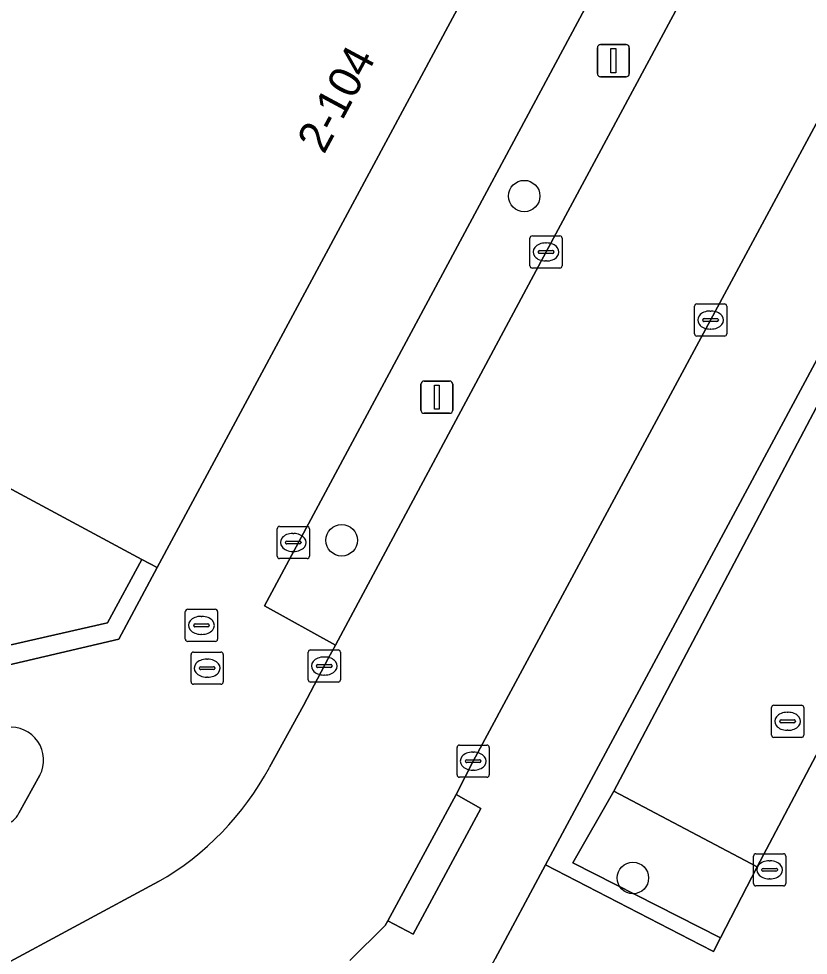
# Model space of a CAD drawing. Extents: x 159489 to 160304, y 383825 to 384531.
# Drawn here: x 159607.69 to 159632.19, y 384161.19 to 384190.24 of the extents above; entities that cross this region are included whole.
import ezdxf

# ---------------------------------------------------------------- set-up
doc = ezdxf.new("R2010")
doc.units = 0
for name, color, linetype in [('IMGEO_Boom', 7, 'Continuous'), ('IMGEO_Erf', 7, 'Continuous'), ('IMGEO_Groenvoorziening', 7, 'Continuous'), ('IMGEO_Haag', 7, 'Continuous'), ('IMGEO_Kolk', 7, 'Continuous'), ('IMGEO_Lichtmast', 7, 'Continuous'), ('IMGEO_Pand', 7, 'Continuous'), ('IMGEO_Pand_nummerreeks', 7, 'Continuous'), ('IMGEO_Parkeervlak_open', 7, 'Continuous'), ('IMGEO_Rijbaan_lokaal_gesloten', 7, 'Continuous'), ('IMGEO_Rijbaan_lokaal_open', 7, 'Continuous'), ('IMGEO_Rioolput', 7, 'Continuous'), ('IMGEO_Voetpad_open', 7, 'Continuous')]:
    doc.layers.add(name, color=color, linetype=linetype)

msp = doc.modelspace()

# ---------------------------------------------------------------- linework, layer by layer
at = {"layer": 'IMGEO_Boom'}
for centre in [(159623.374, 384184.738), (159617.709, 384174.062), (159626.747, 384163.584)]:
    msp.add_circle(centre, 0.489, dxfattribs=at)
at = {"layer": 'IMGEO_Erf'}
msp.add_lwpolyline([(159585.772, 384220.436), (159598.102, 384213.824), (159584.34, 384188.267), (159591.297, 384176.816), (159590.869, 384176.557), (159592.722, 384173.505), (159593.148, 384173.767), (159596.495, 384168.323), (159610.44, 384171.495), (159611.51, 384173.469), (159596.947, 384181.297), (159609.875, 384205.335), (159601.626, 384209.778), (159602.531, 384211.447), (159614.722, 384234.18)], dxfattribs=at)
at = {"layer": 'IMGEO_Groenvoorziening'}
for points in [[(159637.45, 384187.678), (159638.592, 384189.885), (159647.537, 384206.76), (159652.006, 384204.401), (159652.186, 384204.749), (159647.326, 384207.335), (159624.039, 384163.992), (159628.847, 384161.508), (159629.249, 384161.301), (159629.469, 384161.725), (159624.879, 384164.058), (159626.156, 384166.276)], [(159631.422, 384196.726), (159631.805, 384197.437), (159629.581, 384198.613), (159615.312, 384172.029), (159617.514, 384170.805), (159624.053, 384183.005)], [(159611.986, 384173.213), (159611.51, 384173.469), (159610.44, 384171.495), (159596.495, 384168.323), (159593.148, 384173.767), (159592.722, 384173.505), (159596.345, 384167.614), (159610.792, 384170.994)], [(159626.156, 384166.276), (159624.879, 384164.058), (159629.469, 384161.725), (159630.608, 384163.927)]]:
    msp.add_lwpolyline(points, close=True, dxfattribs=at)
msp.add_lwpolyline([(159607.686, 384165.591), (159608.344, 384166.77)], dxfattribs=at)
for centre, radius, start, end in [((159607.432, 384167.239), 1.025, 332.7949, 96.4671), ((159607.102, 384165.875), 0.65, 286.2159, 334.0909)]:
    msp.add_arc(centre, radius, start, end, dxfattribs=at)
at = {"layer": 'IMGEO_Haag'}
msp.add_lwpolyline([(159637.45, 384187.678), (159638.592, 384189.885), (159647.537, 384206.76), (159652.006, 384204.401), (159652.186, 384204.749), (159647.326, 384207.335), (159624.039, 384163.992), (159628.847, 384161.508), (159629.249, 384161.301), (159629.469, 384161.725), (159624.879, 384164.058), (159626.156, 384166.276)], close=True, dxfattribs=at)
at = {"layer": 'IMGEO_Kolk'}
for p, q in [((159623.552, 384182.579), (159623.552, 384183.431)), ((159623.627, 384183.505), (159624.479, 384183.505)), ((159624.04, 384183.285), (159624.065, 384183.285)), ((159624.553, 384183.431), (159624.553, 384182.579)), ((159623.811, 384182.999), (159623.811, 384183.011)), ((159624.249, 384182.962), (159623.851, 384182.962)), ((159623.854, 384183.048), (159624.252, 384183.048)), ((159624.295, 384183.011), (159624.295, 384182.999)), ((159624.063, 384182.725), (159624.038, 384182.725)), ((159624.479, 384182.505), (159623.627, 384182.505)), ((159628.659, 384180.467), (159628.659, 384181.319)), ((159628.734, 384181.393), (159629.586, 384181.393)), ((159629.66, 384181.319), (159629.66, 384180.467)), ((159628.961, 384180.936), (159629.359, 384180.936)), ((159629.147, 384181.173), (159629.172, 384181.173)), ((159628.918, 384180.887), (159628.918, 384180.899)), ((159629.356, 384180.85), (159628.958, 384180.85)), ((159629.402, 384180.899), (159629.402, 384180.887)), ((159629.586, 384180.393), (159628.734, 384180.393)), ((159629.17, 384180.613), (159629.145, 384180.613)), ((159615.707, 384173.567), (159615.707, 384174.419)), ((159615.782, 384174.493), (159616.634, 384174.493)), ((159616.195, 384174.273), (159616.22, 384174.273)), ((159616.708, 384174.419), (159616.708, 384173.567)), ((159615.966, 384173.987), (159615.966, 384173.999)), ((159616.009, 384174.036), (159616.407, 384174.036)), ((159616.45, 384173.999), (159616.45, 384173.987)), ((159616.404, 384173.95), (159616.006, 384173.95)), ((159616.218, 384173.713), (159616.193, 384173.713)), ((159616.634, 384173.493), (159615.782, 384173.493)), ((159616.67, 384169.734), (159616.67, 384170.586)), ((159616.745, 384170.66), (159617.597, 384170.66)), ((159617.671, 384170.586), (159617.671, 384169.734)), ((159616.972, 384170.203), (159617.37, 384170.203)), ((159617.158, 384170.44), (159617.183, 384170.44)), ((159616.929, 384170.154), (159616.929, 384170.166)), ((159617.367, 384170.117), (159616.969, 384170.117)), ((159617.413, 384170.166), (159617.413, 384170.154)), ((159617.597, 384169.66), (159616.745, 384169.66)), ((159617.181, 384169.88), (159617.156, 384169.88)), ((159621.29, 384166.783), (159621.29, 384167.635)), ((159621.365, 384167.709), (159622.217, 384167.709)), ((159622.291, 384167.635), (159622.291, 384166.783)), ((159621.778, 384167.489), (159621.803, 384167.489)), ((159621.549, 384167.203), (159621.549, 384167.215)), ((159621.987, 384167.166), (159621.589, 384167.166)), ((159621.592, 384167.252), (159621.99, 384167.252)), ((159622.033, 384167.215), (159622.033, 384167.203)), ((159622.217, 384166.709), (159621.365, 384166.709)), ((159621.801, 384166.929), (159621.776, 384166.929)), ((159630.492, 384163.411), (159630.492, 384164.263)), ((159630.567, 384164.337), (159631.419, 384164.337)), ((159630.98, 384164.117), (159631.005, 384164.117)), ((159631.493, 384164.263), (159631.493, 384163.411)), ((159630.751, 384163.831), (159630.751, 384163.843)), ((159631.189, 384163.794), (159630.791, 384163.794)), ((159630.794, 384163.88), (159631.192, 384163.88)), ((159631.235, 384163.843), (159631.235, 384163.831)), ((159631.003, 384163.557), (159630.978, 384163.557)), ((159631.419, 384163.337), (159630.567, 384163.337))]:
    msp.add_line(p, q, dxfattribs=at)
for points in [[(159623.552, 384182.579), (159623.552, 384183.431)], [(159623.627, 384183.505), (159624.479, 384183.505)], [(159624.553, 384183.431), (159624.553, 384182.579)], [(159624.479, 384182.505), (159623.627, 384182.505)], [(159628.659, 384180.467), (159628.659, 384181.319)], [(159628.734, 384181.393), (159629.586, 384181.393)], [(159629.66, 384181.319), (159629.66, 384180.467)], [(159629.586, 384180.393), (159628.734, 384180.393)], [(159615.707, 384173.567), (159615.707, 384174.419)], [(159615.782, 384174.493), (159616.634, 384174.493)], [(159616.708, 384174.419), (159616.708, 384173.567)], [(159616.634, 384173.493), (159615.782, 384173.493)], [(159616.67, 384169.734), (159616.67, 384170.586)], [(159616.745, 384170.66), (159617.597, 384170.66)], [(159617.671, 384170.586), (159617.671, 384169.734)], [(159617.597, 384169.66), (159616.745, 384169.66)], [(159621.29, 384166.783), (159621.29, 384167.635)], [(159621.365, 384167.709), (159622.217, 384167.709)], [(159622.291, 384167.635), (159622.291, 384166.783)], [(159622.217, 384166.709), (159621.365, 384166.709)], [(159630.492, 384163.411), (159630.492, 384164.263)], [(159630.567, 384164.337), (159631.419, 384164.337)], [(159631.493, 384164.263), (159631.493, 384163.411)], [(159631.419, 384163.337), (159630.567, 384163.337)]]:
    msp.add_lwpolyline(points, dxfattribs=at)
for centre, radius, start, end in [((159623.629, 384183.429), 0.0765, 91.552, 178.448), ((159623.629, 384183.429), 0.0765, 91.552, 178.448), ((159624.477, 384183.429), 0.0765, 1.552, 88.448), ((159624.477, 384183.429), 0.0765, 1.552, 88.448), ((159623.851, 384183.008), 0.0403, 85.8775, 175.7526), ((159623.848, 384182.998), 0.0366, 178.938, 274.7102), ((159624.252, 384183.005), 0.043, 264.8664, 352.4533), ((159624.256, 384183.01), 0.0386, 1.7309, 96.639), ((159623.629, 384182.581), 0.0765, 181.552, 268.448), ((159623.629, 384182.581), 0.0765, 181.552, 268.448), ((159624.477, 384182.581), 0.0765, 271.552, 358.448), ((159624.477, 384182.581), 0.0765, 271.552, 358.448), ((159628.736, 384181.317), 0.0765, 91.552, 178.448), ((159628.736, 384181.317), 0.0765, 91.552, 178.448), ((159629.584, 384181.317), 0.0765, 1.552, 88.448), ((159629.584, 384181.317), 0.0765, 1.552, 88.448), ((159628.958, 384180.896), 0.0403, 85.8775, 175.7526), ((159629.363, 384180.898), 0.0386, 1.7309, 96.639), ((159628.955, 384180.886), 0.0366, 178.938, 274.7102), ((159629.359, 384180.893), 0.043, 264.8664, 352.4533), ((159628.736, 384180.469), 0.0765, 181.552, 268.448), ((159628.736, 384180.469), 0.0765, 181.552, 268.448), ((159629.584, 384180.469), 0.0765, 271.552, 358.448), ((159629.584, 384180.469), 0.0765, 271.552, 358.448), ((159615.784, 384174.417), 0.0765, 91.552, 178.448), ((159615.784, 384174.417), 0.0765, 91.552, 178.448), ((159616.632, 384174.417), 0.0765, 1.552, 88.448), ((159616.632, 384174.417), 0.0765, 1.552, 88.448), ((159616.006, 384173.996), 0.0403, 85.8775, 175.7526), ((159616.003, 384173.986), 0.0366, 178.938, 274.7102), ((159616.407, 384173.993), 0.043, 264.8664, 352.4533), ((159616.411, 384173.998), 0.0386, 1.7309, 96.639), ((159615.784, 384173.569), 0.0765, 181.552, 268.448), ((159615.784, 384173.569), 0.0765, 181.552, 268.448), ((159616.632, 384173.569), 0.0765, 271.552, 358.448), ((159616.632, 384173.569), 0.0765, 271.552, 358.448), ((159616.747, 384170.584), 0.0765, 91.552, 178.448), ((159616.747, 384170.584), 0.0765, 91.552, 178.448), ((159617.595, 384170.584), 0.0765, 1.552, 88.448), ((159617.595, 384170.584), 0.0765, 1.552, 88.448), ((159616.969, 384170.163), 0.0403, 85.8775, 175.7526), ((159617.374, 384170.165), 0.0386, 1.7309, 96.639), ((159616.966, 384170.153), 0.0366, 178.938, 274.7102), ((159617.37, 384170.16), 0.043, 264.8664, 352.4533), ((159616.747, 384169.736), 0.0765, 181.552, 268.448), ((159616.747, 384169.736), 0.0765, 181.552, 268.448), ((159617.595, 384169.736), 0.0765, 271.552, 358.448), ((159617.595, 384169.736), 0.0765, 271.552, 358.448), ((159621.367, 384167.633), 0.0765, 91.552, 178.448), ((159621.367, 384167.633), 0.0765, 91.552, 178.448), ((159622.215, 384167.633), 0.0765, 1.552, 88.448), ((159622.215, 384167.633), 0.0765, 1.552, 88.448), ((159621.589, 384167.212), 0.0403, 85.8775, 175.7526), ((159621.586, 384167.202), 0.0366, 178.938, 274.7102), ((159621.99, 384167.209), 0.043, 264.8664, 352.4533), ((159621.994, 384167.214), 0.0386, 1.7309, 96.639), ((159621.367, 384166.785), 0.0765, 181.552, 268.448), ((159621.367, 384166.785), 0.0765, 181.552, 268.448), ((159622.215, 384166.785), 0.0765, 271.552, 358.448), ((159622.215, 384166.785), 0.0765, 271.552, 358.448), ((159630.569, 384164.261), 0.0765, 91.552, 178.448), ((159630.569, 384164.261), 0.0765, 91.552, 178.448), ((159631.417, 384164.261), 0.0765, 1.552, 88.448), ((159631.417, 384164.261), 0.0765, 1.552, 88.448), ((159630.791, 384163.84), 0.0403, 85.8775, 175.7526), ((159630.788, 384163.83), 0.0366, 178.938, 274.7102), ((159631.192, 384163.837), 0.043, 264.8664, 352.4533), ((159631.196, 384163.842), 0.0386, 1.7309, 96.639), ((159630.569, 384163.413), 0.0765, 181.552, 268.448), ((159630.569, 384163.413), 0.0765, 181.552, 268.448), ((159631.417, 384163.413), 0.0765, 271.552, 358.448), ((159631.417, 384163.413), 0.0765, 271.552, 358.448)]:
    msp.add_arc(centre, radius, start, end, dxfattribs=at)
for centre, major_axis, ratio, start_param, end_param in [((159624.039, 384183.005), (-0.387, 0.002), 0.722429, 4.712389, 7.853982), ((159624.064, 384183.005), (-0.39, 0.002), 0.717154, 1.570796, 4.712389), ((159629.146, 384180.893), (-0.387, 0.002), 0.722429, 4.712389, 7.853982), ((159629.171, 384180.893), (-0.39, 0.002), 0.717154, 1.570796, 4.712389), ((159616.194, 384173.993), (-0.387, 0.002), 0.722429, 4.712389, 7.853982), ((159616.219, 384173.993), (-0.39, 0.002), 0.717154, 1.570796, 4.712389), ((159617.157, 384170.16), (-0.387, 0.002), 0.722429, 4.712389, 7.853982), ((159617.182, 384170.16), (-0.39, 0.002), 0.717154, 1.570796, 4.712389), ((159621.777, 384167.209), (-0.387, 0.002), 0.722429, 4.712389, 7.853982), ((159621.802, 384167.209), (-0.39, 0.002), 0.717154, 1.570796, 4.712389), ((159630.979, 384163.837), (-0.387, 0.002), 0.722429, 4.712389, 7.853982), ((159631.004, 384163.837), (-0.39, 0.002), 0.717154, 1.570796, 4.712389)]:
    msp.add_ellipse(centre, major_axis=major_axis, ratio=ratio, start_param=start_param, end_param=end_param, dxfattribs=at)
at = {"layer": 'IMGEO_Lichtmast'}
for p, q in [((159625.746, 384189.44), (159626.536, 384189.44)), ((159626.536, 384189.44), (159625.746, 384189.44)), ((159625.646, 384188.54), (159625.646, 384189.34)), ((159625.646, 384189.34), (159625.646, 384188.54)), ((159626.636, 384189.34), (159626.636, 384188.54)), ((159626.636, 384188.54), (159626.636, 384189.34)), ((159626.536, 384188.44), (159625.746, 384188.44)), ((159625.746, 384188.44), (159626.536, 384188.44)), ((159620.169, 384178.1), (159620.169, 384178.9)), ((159620.169, 384178.9), (159620.169, 384178.1)), ((159620.269, 384179), (159621.059, 384179)), ((159621.059, 384179), (159620.269, 384179)), ((159621.159, 384178.9), (159621.159, 384178.1)), ((159621.159, 384178.1), (159621.159, 384178.9)), ((159621.059, 384178), (159620.269, 384178)), ((159620.269, 384178), (159621.059, 384178))]:
    msp.add_line(p, q, dxfattribs=at)
for points in [[(159626.066, 384189.315), (159626.216, 384189.315), (159626.216, 384188.565), (159626.066, 384188.565), (159626.066, 384189.315)], [(159620.589, 384178.875), (159620.739, 384178.875), (159620.739, 384178.125), (159620.589, 384178.125), (159620.589, 384178.875)]]:
    msp.add_lwpolyline(points, dxfattribs=at)
for centre, start, end in [((159625.746, 384189.34), 90, 180), ((159625.746, 384189.34), 90, 180), ((159626.536, 384189.34), 0, 90), ((159626.536, 384189.34), 360, 90), ((159625.746, 384188.54), 180, 270), ((159625.746, 384188.54), 180, 270), ((159626.536, 384188.54), 270, 0), ((159626.536, 384188.54), 270, 0), ((159620.269, 384178.9), 90, 180), ((159620.269, 384178.9), 90, 180), ((159621.059, 384178.9), 0, 90), ((159621.059, 384178.9), 360, 90), ((159620.269, 384178.1), 180, 270), ((159620.269, 384178.1), 180, 270), ((159621.059, 384178.1), 270, 0), ((159621.059, 384178.1), 270, 0)]:
    msp.add_arc(centre, 0.1, start, end, dxfattribs=at)
at = {"layer": 'IMGEO_Pand'}
msp.add_lwpolyline([(159618.808, 384205.718), (159623.257, 384213.945), (159629.821, 384226.083), (159614.722, 384234.18), (159602.531, 384211.447), (159601.626, 384209.778), (159609.875, 384205.335), (159596.947, 384181.297), (159611.51, 384173.469), (159611.986, 384173.213), (159614.197, 384177.327), (159627.071, 384201.275)], close=True, dxfattribs=at)
at = {"layer": 'IMGEO_Parkeervlak_open'}
msp.add_lwpolyline([(159641.925, 384185.331), (159637.45, 384187.678), (159626.156, 384166.276), (159630.608, 384163.927)], close=True, dxfattribs=at)
at = {"layer": 'IMGEO_Rijbaan_lokaal_gesloten'}
for points in [[(159654.684, 384240.484), (159653.747, 384238.682), (159646.166, 384224.11), (159643.655, 384219.446), (159639.366, 384211.481), (159638.312, 384209.524), (159635.354, 384204.03), (159631.805, 384197.437), (159631.422, 384196.726), (159624.053, 384183.005), (159617.514, 384170.805), (159617.293, 384170.392), (159616.523, 384168.93), (159615.471, 384167.017)], [(159617.96, 384161.026), (159619.063, 384162.111), (159619.143, 384162.254), (159621.259, 384166.179), (159621.791, 384167.209), (159629.16, 384180.893), (159636.525, 384194.583)], [(159612.028, 384163.471), (159602.037, 384158.093), (159601.646, 384157.893), (159598.777, 384156.375)]]:
    msp.add_lwpolyline(points, dxfattribs=at)
msp.add_arc((159607.481, 384171.33), 9.08, 300.0512, 331.6375, dxfattribs=at)
at = {"layer": 'IMGEO_Rijbaan_lokaal_open'}
msp.add_lwpolyline([(159674.044, 384201.652), (159651.431, 384213.623), (159649.663, 384210.272), (159649.078, 384210.598), (159647.326, 384207.335), (159652.186, 384204.749), (159652.006, 384204.401), (159643.082, 384187.51), (159641.925, 384185.331), (159630.608, 384163.927), (159629.469, 384161.725), (159629.249, 384161.301), (159628.847, 384161.508), (159624.039, 384163.992), (159622.471, 384161.072)], dxfattribs=at)
at = {"layer": 'IMGEO_Rioolput'}
for p, q in [((159612.932, 384171.921), (159613.784, 384171.921)), ((159612.857, 384170.995), (159612.857, 384171.847)), ((159613.345, 384171.701), (159613.37, 384171.701)), ((159613.858, 384171.847), (159613.858, 384170.995)), ((159613.116, 384171.415), (159613.116, 384171.427)), ((159613.554, 384171.378), (159613.156, 384171.378)), ((159613.159, 384171.464), (159613.557, 384171.464)), ((159613.6, 384171.427), (159613.6, 384171.415)), ((159613.368, 384171.141), (159613.343, 384171.141)), ((159613.784, 384170.921), (159612.932, 384170.921)), ((159613.034, 384169.667), (159613.034, 384170.519)), ((159613.109, 384170.593), (159613.961, 384170.593)), ((159614.035, 384170.519), (159614.035, 384169.667)), ((159613.522, 384170.373), (159613.547, 384170.373)), ((159613.293, 384170.087), (159613.293, 384170.099)), ((159613.731, 384170.05), (159613.333, 384170.05)), ((159613.336, 384170.136), (159613.734, 384170.136)), ((159613.777, 384170.099), (159613.777, 384170.087)), ((159613.545, 384169.813), (159613.52, 384169.813)), ((159613.961, 384169.593), (159613.109, 384169.593)), ((159631.05, 384168.019), (159631.05, 384168.871)), ((159631.125, 384168.945), (159631.977, 384168.945)), ((159631.538, 384168.725), (159631.563, 384168.725)), ((159632.051, 384168.871), (159632.051, 384168.019)), ((159631.309, 384168.439), (159631.309, 384168.451)), ((159631.352, 384168.488), (159631.75, 384168.488)), ((159631.793, 384168.451), (159631.793, 384168.439)), ((159631.747, 384168.402), (159631.349, 384168.402)), ((159631.561, 384168.165), (159631.536, 384168.165)), ((159631.977, 384167.945), (159631.125, 384167.945))]:
    msp.add_line(p, q, dxfattribs=at)
for points in [[(159612.932, 384171.921), (159613.784, 384171.921)], [(159612.857, 384170.995), (159612.857, 384171.847)], [(159613.858, 384171.847), (159613.858, 384170.995)], [(159613.784, 384170.921), (159612.932, 384170.921)], [(159613.034, 384169.667), (159613.034, 384170.519)], [(159613.109, 384170.593), (159613.961, 384170.593)], [(159614.035, 384170.519), (159614.035, 384169.667)], [(159613.961, 384169.593), (159613.109, 384169.593)], [(159631.05, 384168.019), (159631.05, 384168.871)], [(159631.125, 384168.945), (159631.977, 384168.945)], [(159632.051, 384168.871), (159632.051, 384168.019)], [(159631.977, 384167.945), (159631.125, 384167.945)]]:
    msp.add_lwpolyline(points, dxfattribs=at)
for centre, radius, start, end in [((159612.934, 384171.845), 0.0765, 91.552, 178.448), ((159612.934, 384171.845), 0.0765, 91.552, 178.448), ((159613.782, 384171.845), 0.0765, 1.552, 88.448), ((159613.782, 384171.845), 0.0765, 1.552, 88.448), ((159613.156, 384171.424), 0.0403, 85.8775, 175.7526), ((159613.153, 384171.414), 0.0366, 178.938, 274.7102), ((159613.557, 384171.421), 0.043, 264.8664, 352.4533), ((159613.561, 384171.426), 0.0386, 1.7309, 96.639), ((159612.934, 384170.997), 0.0765, 181.552, 268.448), ((159612.934, 384170.997), 0.0765, 181.552, 268.448), ((159613.782, 384170.997), 0.0765, 271.552, 358.448), ((159613.782, 384170.997), 0.0765, 271.552, 358.448), ((159613.111, 384170.517), 0.0765, 91.552, 178.448), ((159613.111, 384170.517), 0.0765, 91.552, 178.448), ((159613.959, 384170.517), 0.0765, 1.552, 88.448), ((159613.959, 384170.517), 0.0765, 1.552, 88.448), ((159613.333, 384170.096), 0.0403, 85.8775, 175.7526), ((159613.33, 384170.086), 0.0366, 178.938, 274.7102), ((159613.734, 384170.093), 0.043, 264.8664, 352.4533), ((159613.738, 384170.098), 0.0386, 1.7309, 96.639), ((159613.111, 384169.669), 0.0765, 181.552, 268.448), ((159613.111, 384169.669), 0.0765, 181.552, 268.448), ((159613.959, 384169.669), 0.0765, 271.552, 358.448), ((159613.959, 384169.669), 0.0765, 271.552, 358.448), ((159631.127, 384168.869), 0.0765, 91.552, 178.448), ((159631.127, 384168.869), 0.0765, 91.552, 178.448), ((159631.975, 384168.869), 0.0765, 1.552, 88.448), ((159631.975, 384168.869), 0.0765, 1.552, 88.448), ((159631.349, 384168.448), 0.0403, 85.8775, 175.7526), ((159631.346, 384168.438), 0.0366, 178.938, 274.7102), ((159631.75, 384168.445), 0.043, 264.8664, 352.4533), ((159631.754, 384168.45), 0.0386, 1.7309, 96.639), ((159631.127, 384168.021), 0.0765, 181.552, 268.448), ((159631.127, 384168.021), 0.0765, 181.552, 268.448), ((159631.975, 384168.021), 0.0765, 271.552, 358.448), ((159631.975, 384168.021), 0.0765, 271.552, 358.448)]:
    msp.add_arc(centre, radius, start, end, dxfattribs=at)
for centre, major_axis, ratio, start_param, end_param in [((159613.344, 384171.421), (-0.387, 0.002), 0.722429, 4.712389, 7.853982), ((159613.369, 384171.421), (-0.39, 0.002), 0.717154, 1.570796, 4.712389), ((159613.521, 384170.093), (-0.387, 0.002), 0.722429, 4.712389, 7.853982), ((159613.546, 384170.093), (-0.39, 0.002), 0.717154, 1.570796, 4.712389), ((159631.537, 384168.445), (-0.387, 0.002), 0.722429, 4.712389, 7.853982), ((159631.562, 384168.445), (-0.39, 0.002), 0.717154, 1.570796, 4.712389)]:
    msp.add_ellipse(centre, major_axis=major_axis, ratio=ratio, start_param=start_param, end_param=end_param, dxfattribs=at)
at = {"layer": 'IMGEO_Voetpad_open'}
for points in [[(159637.113, 384212.661), (159639.366, 384211.481), (159643.655, 384219.446), (159641.422, 384220.631), (159651.736, 384239.768), (159653.747, 384238.682), (159654.684, 384240.484), (159649.079, 384242.048), (159640.276, 384225.681), (159631.56, 384209.476), (159627.071, 384201.275), (159614.197, 384177.327), (159611.986, 384173.213), (159610.792, 384170.994), (159596.345, 384167.614), (159594.181, 384167.108), (159595.735, 384164.295)], [(159647.326, 384207.335), (159649.078, 384210.598), (159649.663, 384210.272), (159651.431, 384213.623), (159651.297, 384213.694), (159651.4, 384213.888), (159648.7, 384215.354), (159644.915, 384208.328), (159644.131, 384208.747), (159643.404, 384207.416), (159642.138, 384205.059), (159640.5, 384205.922), (159639.307, 384203.695), (159640.934, 384202.788), (159636.525, 384194.583), (159629.16, 384180.893), (159621.791, 384167.209), (159621.259, 384166.179), (159622.029, 384165.74), (159619.927, 384161.842), (159619.143, 384162.254), (159619.063, 384162.111), (159617.96, 384161.026)], [(159615.471, 384167.017), (159616.523, 384168.93), (159617.293, 384170.392), (159617.514, 384170.805), (159615.312, 384172.029), (159629.581, 384198.613), (159633.141, 384205.225), (159637.113, 384212.661)], [(159613.734, 384158.126), (159604.421, 384153.122), (159601.595, 384151.633), (159604.764, 384149.496), (159618.169, 384156.621), (159620.642, 384157.928), (159622.146, 384160.474), (159622.471, 384161.072), (159624.039, 384163.992), (159647.326, 384207.335)], [(159608.344, 384166.77), (159607.686, 384165.591)], [(159597.049, 384161.911), (159598.777, 384156.375), (159601.646, 384157.893), (159602.037, 384158.093), (159612.028, 384163.471)]]:
    msp.add_lwpolyline(points, dxfattribs=at)
msp.add_lwpolyline([(159621.259, 384166.179), (159619.143, 384162.254), (159619.927, 384161.842), (159622.029, 384165.74)], close=True, dxfattribs=at)
for centre, radius, start, end in [((159607.432, 384167.239), 1.025, 332.7949, 96.4671), ((159607.481, 384171.33), 9.08, 300.0512, 331.6375), ((159607.102, 384165.875), 0.65, 286.2159, 334.0909)]:
    msp.add_arc(centre, radius, start, end, dxfattribs=at)

# ---------------------------------------------------------------- texts
at = {"layer": 'IMGEO_Pand_nummerreeks'}
msp.add_text('2-104', height=1, rotation=61.7305, dxfattribs=at).set_placement((159617.162, 384186.011))

doc.saveas('drawing.dxf')
